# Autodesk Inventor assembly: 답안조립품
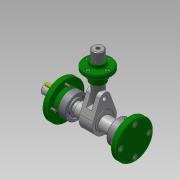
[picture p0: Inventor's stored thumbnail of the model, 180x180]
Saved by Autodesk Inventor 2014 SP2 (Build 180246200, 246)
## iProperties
Created: 2016-08
Part Number: 답안조립품
Document SubType Name: Assembly
Designer: user
Author: user
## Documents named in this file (13)
- C:\Users\user\Desktop\460820V1022\답안조립품.iam
- C:\Users\user\Desktop\460820V1022\본체.ipt
- C:\Users\user\Desktop\460820V1022\편심축.ipt
- C:\Users\user\Desktop\460820V1022\베어링 15 x 35 x 11.ipt
- C:\Users\user\Desktop\460820V1022\앞커버.ipt
- C:\Users\user\Desktop\460820V1022\뒤커버.ipt
- C:\Users\user\Desktop\460820V1022\볼트 M4 x 10.ipt
- C:\Users\user\Desktop\460820V1022\오일실 15 25 7.ipt
- C:\Users\user\Desktop\460820V1022\링크.ipt
- C:\Users\user\Desktop\460820V1022\슬라이드바.ipt
- C:\Users\user\Desktop\460820V1022\상부부시.ipt
- C:\Users\user\Desktop\460820V1022\볼트 M3 x 8.ipt
- C:\Users\user\Desktop\460820V1022\키 5 x 5 x 14.ipt
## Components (12 placed, 2 different names)
1. ISO 4762 M4 x 10:1 — 강체:4
2. ISO 4762 M4 x 10:2 — 강체:3
3. ISO 4762 M4 x 10:3 — 강체:2
4. ISO 4762 M4 x 10:4 — 강체:1
5. ISO 4762 M4 x 10:5 — 강체:6
6. ISO 4762 M4 x 10:6 — 강체:5
7. ISO 4762 M4 x 10:7 — 강체:7
8. ISO 4762 M4 x 10:8 — 강체:8
9. ISO 4762 M3 x 8:1 — 강체:11
10. ISO 4762 M3 x 8:2 — 강체:9
11. ISO 4762 M3 x 8:3 — 강체:10
12. ISO 4762 M3 x 8:4 — 강체:12
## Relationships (12: WeldJoint 12)
- 강체:1 [WeldJoint]: ISO 4762 M4 x 10:4
- 강체:2 [WeldJoint]: ISO 4762 M4 x 10:3
- 강체:3 [WeldJoint]: ISO 4762 M4 x 10:2
- 강체:4 [WeldJoint]: ISO 4762 M4 x 10:1
- 강체:5 [WeldJoint]: ISO 4762 M4 x 10:6
- 강체:6 [WeldJoint]: ISO 4762 M4 x 10:5
- 강체:7 [WeldJoint]: ISO 4762 M4 x 10:7
- 강체:8 [WeldJoint]: ISO 4762 M4 x 10:8
- 강체:9 [WeldJoint]: ISO 4762 M3 x 8:2
- 강체:10 [WeldJoint]: ISO 4762 M3 x 8:3
- 강체:11 [WeldJoint]: ISO 4762 M3 x 8:1
- 강체:12 [WeldJoint]: ISO 4762 M3 x 8:4
